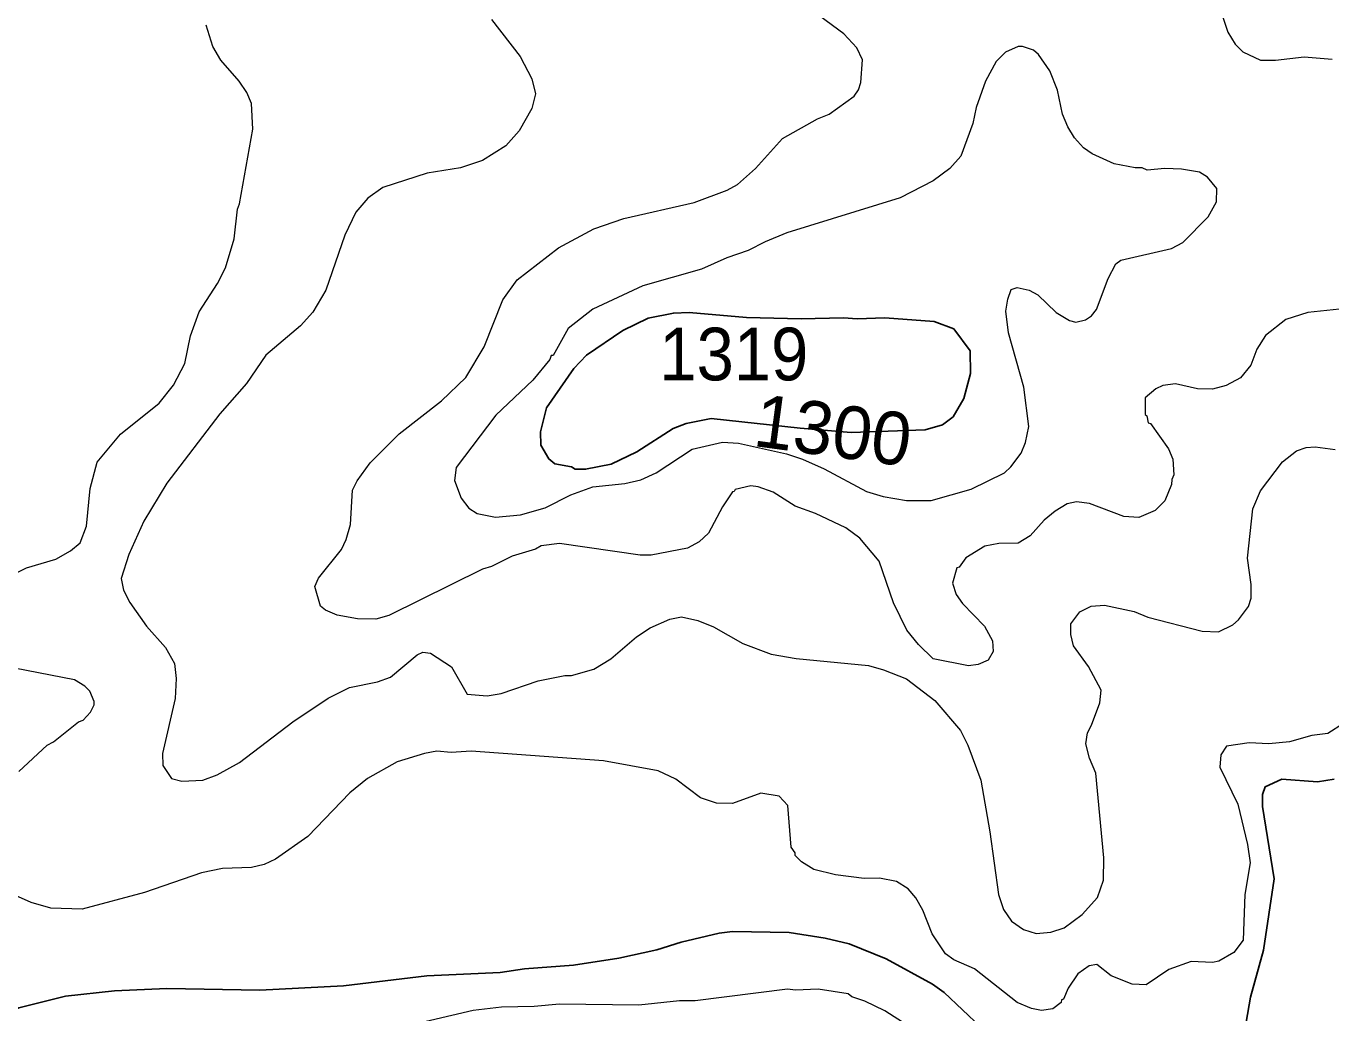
# Model space of a CAD drawing. Extents: x 598.3 to 623.2, y 6902.2 to 6930.1.
# Drawn here: x 600.565 to 602.546, y 6918.158 to 6919.656 of the extents above; entities that cross this region are included whole.
import ezdxf
from ezdxf.enums import TextEntityAlignment as Align

# ---------------------------------------------------------------- set-up
doc = ezdxf.new("R2010")
doc.units = 0
doc.header["$LTSCALE"] = 0.032
doc.layers.add('1', color=7, linetype='Continuous', lineweight=25)
doc.layers.add('2', color=7, linetype='Continuous', lineweight=13)
doc.layers.add('21', color=7, linetype='Continuous')
doc.layers.add('61', color=7, linetype='Continuous')

msp = doc.modelspace()

# ---------------------------------------------------------------- linework, layer by layer
at = {"layer": '1'}
msp.add_lwpolyline([(601.8056, 6919.2132), (601.8265, 6919.2117), (601.8683, 6919.2132), (601.9433, 6919.2077), (601.9732, 6919.1965), (601.998, 6919.163), (601.9988, 6919.1287), (601.9886, 6919.0909), (601.9721, 6919.0628), (601.9559, 6919.0509), (601.9297, 6919.0433), (601.8176, 6919.0389), (601.74, 6919.0454), (601.6046, 6919.0602), (601.5671, 6919.0525), (601.547, 6919.0451), (601.492, 6919.0096), (601.4531, 6918.9909), (601.4142, 6918.9834), (601.3986, 6918.9834), (601.3928, 6918.9868), (601.3675, 6918.9915), (601.3584, 6918.9989), (601.346, 6919.0198), (601.3456, 6919.0403), (601.3551, 6919.0767), (601.3965, 6919.1363), (601.4157, 6919.1563), (601.4705, 6919.1939), (601.5091, 6919.2124), (601.5476, 6919.2204), (601.5712, 6919.2214), (601.6585, 6919.2134), (601.7415, 6919.2117)], close=True, dxfattribs=at)
for points in [[(602.4171, 6918.144), (602.4238, 6918.1819), (602.4432, 6918.2531), (602.4594, 6918.3613), (602.4417, 6918.4714), (602.4417, 6918.4895), (602.4458, 6918.501), (602.471, 6918.513), (602.5251, 6918.509)], [(602.5251, 6918.509), (602.5506, 6918.513)], [(600.5355, 6918.1555), (600.5539, 6918.1657), (600.6248, 6918.1835), (600.6989, 6918.1916), (600.7784, 6918.1949), (600.9198, 6918.1924), (601.0467, 6918.199), (601.1732, 6918.2143), (601.2843, 6918.2192), (601.3216, 6918.2249), (601.3957, 6918.2305), (601.4647, 6918.2411), (601.5223, 6918.2536), (601.5595, 6918.2654), (601.6172, 6918.2792), (601.6374, 6918.2815), (601.7231, 6918.28), (601.7778, 6918.2717), (601.8141, 6918.2626), (601.8704, 6918.2401), (601.9411, 6918.2015), (601.9586, 6918.189), (602.0423, 6918.11)]]:
    msp.add_lwpolyline(points, dxfattribs=at)
at = {"layer": '2'}
for points in [[(601.2714, 6919.666), (601.3149, 6919.6096), (601.3325, 6919.5761), (601.3382, 6919.553), (601.3328, 6919.5311), (601.3133, 6919.4968), (601.2932, 6919.4743), (601.2579, 6919.4519), (601.2244, 6919.4407), (601.1739, 6919.4325), (601.1066, 6919.411), (601.0836, 6919.3948), (601.0653, 6919.3733), (601.0489, 6919.3385), (601.0201, 6919.2553), (601.0001, 6919.2216), (600.9813, 6919.201), (600.9288, 6919.1565), (600.8995, 6919.1137), (600.859, 6919.0675), (600.7784, 6918.9622), (600.7435, 6918.9046), (600.7208, 6918.8538), (600.7093, 6918.8172), (600.7127, 6918.7999), (600.7223, 6918.781), (600.7475, 6918.7451), (600.7766, 6918.7127), (600.7902, 6918.6886), (600.7927, 6918.6655), (600.791, 6918.6352), (600.7717, 6918.5516), (600.7725, 6918.5336), (600.7855, 6918.5139), (600.8014, 6918.5098), (600.833, 6918.5111), (600.8548, 6918.5193), (600.8888, 6918.5379), (600.9699, 6918.5996), (601.0234, 6918.6358), (601.0557, 6918.6522), (601.0981, 6918.6604), (601.1179, 6918.6677), (601.1585, 6918.7016), (601.1673, 6918.7055)], [(602.2685, 6919.0539), (602.2716, 6919.0527), (602.299, 6919.0144), (602.3056, 6918.9987), (602.3073, 6918.9747), (602.304, 6918.9676), (602.3039, 6918.9601), (602.2937, 6918.9353), (602.2789, 6918.9206), (602.2542, 6918.9098), (602.2313, 6918.9114), (602.1794, 6918.9312), (602.1595, 6918.934), (602.1453, 6918.9307), (602.127, 6918.9197), (602.1103, 6918.906), (602.0892, 6918.882), (602.0707, 6918.871), (602.0415, 6918.8708), (602.0202, 6918.8665), (601.9916, 6918.8489), (601.9811, 6918.8346), (601.9778, 6918.8334), (601.9712, 6918.8102), (601.977, 6918.7933), (601.9865, 6918.7795), (602.02, 6918.7451), (602.0319, 6918.7229), (602.0328, 6918.7067), (602.0254, 6918.6936), (602.0101, 6918.6868), (601.9956, 6918.6847), (601.9418, 6918.6955), (601.9197, 6918.717), (601.902, 6918.7392), (601.8817, 6918.7804), (601.8598, 6918.8436), (601.8303, 6918.8789), (601.8094, 6918.8943), (601.763, 6918.9159), (601.7324, 6918.9274), (601.6988, 6918.9484), (601.6764, 6918.9565), (601.6652, 6918.9582), (601.6413, 6918.9525), (601.64, 6918.9494), (601.6371, 6918.9492), (601.6219, 6918.9263), (601.6007, 6918.8865), (601.5866, 6918.8731), (601.5688, 6918.8635), (601.514, 6918.8531), (601.497, 6918.8529), (601.3745, 6918.8708), (601.3468, 6918.8668), (601.338, 6918.8618), (601.3028, 6918.8511), (601.2712, 6918.8358), (601.2579, 6918.8318), (601.1153, 6918.7612), (601.0959, 6918.7558), (601.0681, 6918.7562), (601.0369, 6918.7617), (601.0195, 6918.7692), (601.0118, 6918.7756), (601.0033, 6918.8051), (601.0089, 6918.8181), (601.0437, 6918.8617), (601.0509, 6918.8764), (601.0573, 6918.8992), (601.0604, 6918.9516), (601.0672, 6918.9655), (601.0873, 6918.993), (601.1314, 6919.0368), (601.1955, 6919.0873), (601.2322, 6919.1227), (601.2602, 6919.1689), (601.2887, 6919.2405), (601.3103, 6919.271), (601.3731, 6919.3192), (601.4265, 6919.3484), (601.4721, 6919.3638), (601.579, 6919.3881), (601.6292, 6919.4068), (601.6449, 6919.4154), (601.6723, 6919.4396), (601.713, 6919.4852), (601.7663, 6919.515), (601.7841, 6919.5223), (601.8218, 6919.5494), (601.8285, 6919.559), (601.8319, 6919.5705), (601.8345, 6919.605), (601.8261, 6919.6231), (601.8062, 6919.6445), (601.77, 6919.6712)], [(602.3786, 6919.6789), (602.3892, 6919.6466), (602.4005, 6919.6286), (602.4122, 6919.617), (602.4388, 6919.6043), (602.4616, 6919.6043), (602.5052, 6919.6091), (602.5474, 6919.6057)], [(600.6467, 6918.8716), (600.6565, 6918.897), (600.6623, 6918.954), (600.6726, 6918.9941), (600.7081, 6919.0363), (600.7667, 6919.0838), (600.7885, 6919.111), (600.8057, 6919.1439), (600.8146, 6919.186), (600.8273, 6919.2223), (600.8553, 6919.2655), (600.8677, 6919.2888), (600.8809, 6919.333), (600.8857, 6919.3781), (600.889, 6919.3864), (600.9092, 6919.4996), (600.9069, 6919.5384), (600.9, 6919.5554), (600.8883, 6919.5724), (600.8604, 6919.6043), (600.8483, 6919.625), (600.8384, 6919.6572)], [(602.626, 6919.2334), (602.5107, 6919.2212), (602.4772, 6919.2107), (602.4463, 6919.1863), (602.4333, 6919.1657), (602.424, 6919.1414), (602.4087, 6919.1222), (602.3866, 6919.1106), (602.3658, 6919.1048), (602.3431, 6919.1055), (602.3099, 6919.1128), (602.2904, 6919.1106), (602.2797, 6919.1055), (602.2636, 6919.0916), (602.2636, 6919.0663), (602.2661, 6919.0645), (602.2685, 6919.0539)], [(601.1673, 6918.7055), (601.1789, 6918.704), (601.2106, 6918.6835), (601.2342, 6918.6417), (601.2647, 6918.6394), (601.2862, 6918.6427), (601.3421, 6918.6619), (601.3826, 6918.67), (601.3928, 6918.6701), (601.4268, 6918.6799), (601.4525, 6918.6954), (601.4917, 6918.7287), (601.512, 6918.7426), (601.5421, 6918.7555), (601.56, 6918.759), (601.5847, 6918.7536), (601.6084, 6918.7443), (601.6531, 6918.7186), (601.6958, 6918.7026), (601.734, 6918.6961), (601.8437, 6918.6855), (601.8667, 6918.679), (601.9012, 6918.665), (601.9444, 6918.6321), (601.9836, 6918.5865), (601.9945, 6918.5646), (602.014, 6918.5112), (602.0279, 6918.4329), (602.0409, 6918.3376), (602.0489, 6918.315), (602.0606, 6918.2975), (602.0792, 6918.2846), (602.0982, 6918.2783), (602.1203, 6918.2805), (602.1407, 6918.2873), (602.1679, 6918.3073), (602.1914, 6918.3334), (602.2004, 6918.3595), (602.2011, 6918.3935), (602.1889, 6918.5221), (602.1794, 6918.5446), (602.1736, 6918.5663), (602.176, 6918.5832), (602.1825, 6918.5947), (602.1948, 6918.6289), (602.1971, 6918.6478), (602.1776, 6918.6841), (602.1548, 6918.7154), (602.1511, 6918.7322), (602.1511, 6918.7485), (602.1643, 6918.7667), (602.1817, 6918.7755), (602.2019, 6918.7769), (602.2471, 6918.7672), (602.2677, 6918.7587), (602.3504, 6918.7376), (602.3753, 6918.7365), (602.3968, 6918.7473), (602.4055, 6918.7547), (602.4207, 6918.7751), (602.4246, 6918.7875), (602.4247, 6918.8083), (602.419, 6918.8483), (602.4271, 6918.9234), (602.4386, 6918.9505), (602.4723, 6918.9946), (602.4937, 6919.0114), (602.5081, 6919.0165), (602.5219, 6919.0172), (602.5522, 6919.0134)], [(600.5123, 6918.8079), (600.5653, 6918.8337), (600.6098, 6918.8469), (600.6322, 6918.8593), (600.6467, 6918.8716)], [(600.5538, 6918.5243), (600.5969, 6918.5642), (600.6065, 6918.5694), (600.6446, 6918.5996), (600.6514, 6918.6024), (600.6626, 6918.6147), (600.668, 6918.6256), (600.668, 6918.6307), (600.6615, 6918.6466), (600.6538, 6918.6542), (600.6384, 6918.6634), (600.5472, 6918.6814)], [(602.5647, 6918.5974), (602.5411, 6918.5819), (602.5165, 6918.5793), (602.4828, 6918.5695), (602.4516, 6918.5665)], [(602.4516, 6918.5665), (602.4217, 6918.568), (602.3872, 6918.563), (602.3785, 6918.5496), (602.377, 6918.5311), (602.4044, 6918.4747), (602.4189, 6918.4137), (602.4229, 6918.3856), (602.4149, 6918.3379), (602.4125, 6918.2683), (602.3983, 6918.2498), (602.3756, 6918.2363), (602.3658, 6918.2346), (602.3335, 6918.2362), (602.2997, 6918.2239), (602.2651, 6918.2006), (602.244, 6918.2018), (602.2123, 6918.2145), (602.1904, 6918.2313), (602.1788, 6918.2294), (602.1614, 6918.2173), (602.147, 6918.1957), (602.1396, 6918.179), (602.1365, 6918.1777), (602.1362, 6918.1738), (602.1234, 6918.1643), (602.1063, 6918.1617), (602.0913, 6918.1646), (602.0692, 6918.1738), (602.0045, 6918.2248), (601.9731, 6918.2385), (601.9608, 6918.2477), (601.9402, 6918.2781), (601.9263, 6918.3139), (601.9158, 6918.3328), (601.9041, 6918.3463), (601.8861, 6918.3576), (601.8604, 6918.3624), (601.8372, 6918.362), (601.7938, 6918.3674), (601.7607, 6918.3757), (601.7419, 6918.3871), (601.7325, 6918.3967), (601.7324, 6918.401), (601.7261, 6918.4096), (601.721, 6918.4727), (601.7079, 6918.4872), (601.6804, 6918.4918), (601.6373, 6918.4758), (601.613, 6918.4765), (601.5889, 6918.4844), (601.5512, 6918.513), (601.5245, 6918.5256), (601.4414, 6918.5405), (601.2406, 6918.5551), (601.2099, 6918.5534), (601.1885, 6918.5551), (601.1694, 6918.5519), (601.1279, 6918.5389), (601.083, 6918.5137), (601.0561, 6918.4923), (600.9923, 6918.4259), (600.9436, 6918.3915), (600.9262, 6918.3835), (600.9071, 6918.3787), (600.8631, 6918.377), (600.831, 6918.3706), (600.7447, 6918.3409), (600.6497, 6918.3155), (600.6022, 6918.3172), (600.5724, 6918.3256), (600.5487, 6918.3361)], [(601.9023, 6918.1392), (601.8683, 6918.161), (601.8383, 6918.176), (601.8186, 6918.1826), (601.8129, 6918.1868), (601.7671, 6918.194), (601.7331, 6918.1925), (601.7209, 6918.194), (601.5806, 6918.1763), (601.557, 6918.1762), (601.4951, 6918.1698), (601.3747, 6918.1714), (601.3363, 6918.1675), (601.2867, 6918.1665), (601.2433, 6918.1616), (601.1465, 6918.139)]]:
    msp.add_lwpolyline(points, dxfattribs=at)
msp.add_lwpolyline([(602.1461, 6919.5031), (602.138, 6919.5224), (602.1306, 6919.5588), (602.119, 6919.588), (602.1018, 6919.6129), (602.0944, 6919.6194), (602.0775, 6919.6252), (602.0708, 6919.6251), (602.0516, 6919.6163), (602.0373, 6919.6024), (602.0213, 6919.5724), (602.007, 6919.5324), (602.002, 6919.5079), (601.9839, 6919.4586), (601.9674, 6919.44), (601.9421, 6919.4212), (601.8917, 6919.3953), (601.7198, 6919.342), (601.6866, 6919.3287), (601.661, 6919.3152), (601.6284, 6919.3044), (601.5903, 6919.2869), (601.501, 6919.2617), (601.4254, 6919.2264), (601.3879, 6919.197), (601.365, 6919.1561), (601.3617, 6919.1562), (601.3599, 6919.15), (601.3341, 6919.1185), (601.2777, 6919.0652), (601.2179, 6918.9858), (601.2153, 6918.9664), (601.2254, 6918.9395), (601.2369, 6918.9244), (601.2494, 6918.9162), (601.2773, 6918.9105), (601.3155, 6918.9143), (601.3529, 6918.9246), (601.392, 6918.9442), (601.4252, 6918.9567), (601.474, 6918.9615), (601.498, 6918.9672), (601.5212, 6918.9779), (601.5762, 6919.014), (601.6222, 6919.0246), (601.6465, 6919.023), (601.7193, 6919.0068), (601.7436, 6918.9988), (601.7765, 6918.984), (601.8409, 6918.9494), (601.8661, 6918.9418), (601.9012, 6918.9359), (601.9387, 6918.9356), (601.9994, 6918.9532), (602.05, 6918.9778), (602.0597, 6918.9867), (602.0757, 6919.0077), (602.0822, 6919.0241), (602.087, 6919.0481), (602.0797, 6919.108), (602.0563, 6919.1905), (602.0523, 6919.2232), (602.0552, 6919.2414), (602.0604, 6919.2561), (602.0695, 6919.2593), (602.0874, 6919.2551), (602.1009, 6919.2478), (602.1287, 6919.2211), (602.1488, 6919.2091), (602.1587, 6919.2067), (602.1731, 6919.2101), (602.1822, 6919.216), (602.1897, 6919.2259), (602.2075, 6919.2729), (602.2191, 6919.295), (602.2268, 6919.3007), (602.3036, 6919.3186), (602.321, 6919.3276), (602.3595, 6919.3664), (602.372, 6919.3894), (602.3726, 6919.4095), (602.3586, 6919.4266), (602.3464, 6919.4341), (602.3188, 6919.439), (602.2937, 6919.4399), (602.2668, 6919.4375), (602.2594, 6919.4406), (602.2484, 6919.4407), (602.2169, 6919.4471), (602.1834, 6919.462), (602.1699, 6919.4713), (602.1562, 6919.4866)], close=True, dxfattribs=at)

# ---------------------------------------------------------------- texts
at = {"layer": '21', "width": 0.95}
msp.add_text('1319', height=0.08, dxfattribs=at).set_placement((601.5262, 6919.1182))
at = {"layer": '61'}
msp.add_text('1300', height=0.08, rotation=352.349, dxfattribs=at).set_placement((601.7847, 6919.003), align=Align.CENTER)

doc.saveas('drawing.dxf')
